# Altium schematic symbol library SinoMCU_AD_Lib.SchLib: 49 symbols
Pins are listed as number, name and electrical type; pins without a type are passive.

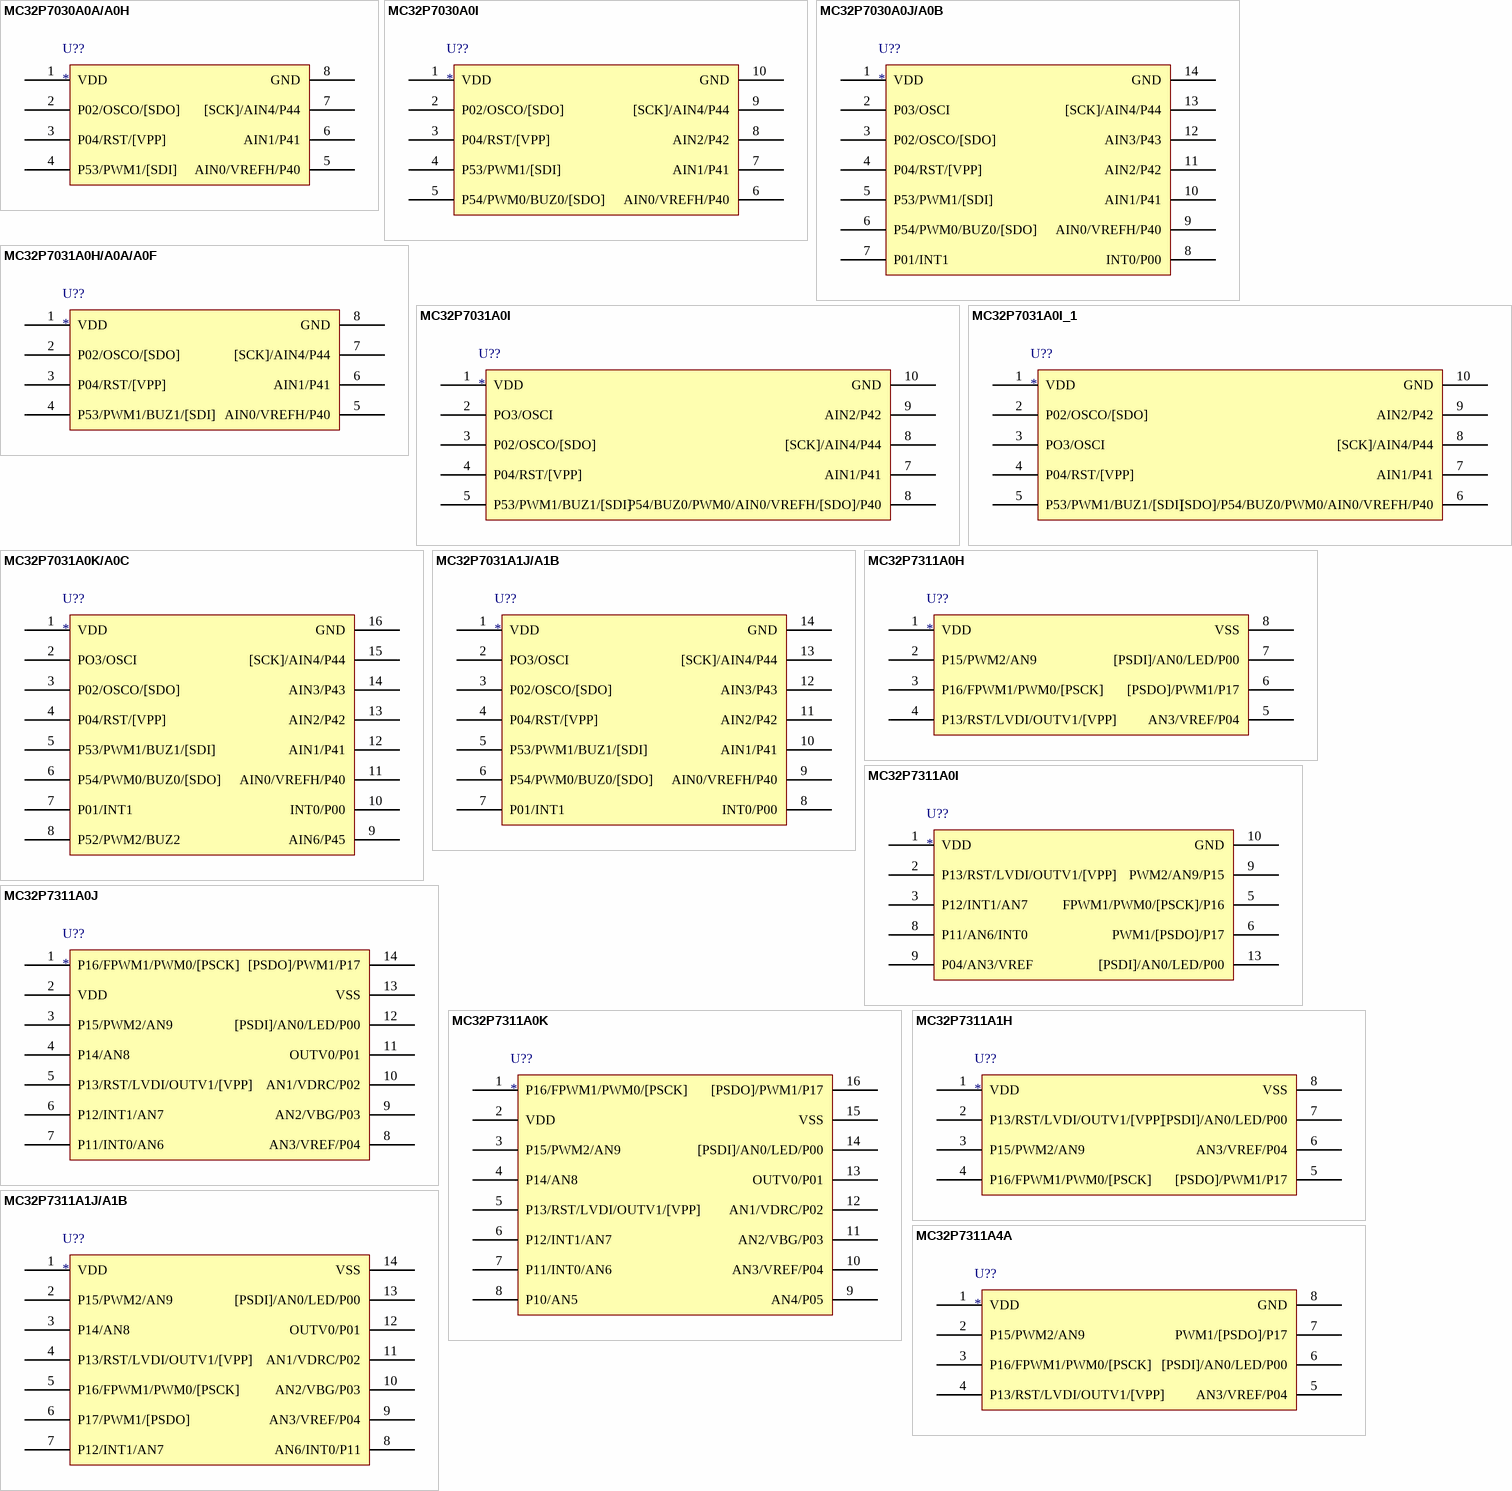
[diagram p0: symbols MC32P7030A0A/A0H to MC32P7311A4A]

## MC32P7030A0A/A0H
designator U??
pins: 1 VDD, 2 P02/OSCO/[SDO], 3 P04/RST/[VPP], 4 P53/PWM1/[SDI], 5 AIN0/VREFH/P40, 6 AIN1/P41, 7 [SCK]/AIN4/P44, 8 GND

## MC32P7030A0I
designator U??
pins: 1 VDD, 2 P02/OSCO/[SDO], 3 P04/RST/[VPP], 4 P53/PWM1/[SDI], 5 P54/PWM0/BUZ0/[SDO], 6 AIN0/VREFH/P40, 7 AIN1/P41, 8 AIN2/P42, 9 [SCK]/AIN4/P44, 10 GND

## MC32P7030A0J/A0B
designator U??
pins: 1 VDD, 2 P03/OSCI, 3 P02/OSCO/[SDO], 4 P04/RST/[VPP], 5 P53/PWM1/[SDI], 6 P54/PWM0/BUZ0/[SDO], 7 P01/INT1, 8 INT0/P00, 9 AIN0/VREFH/P40, 10 AIN1/P41, 11 AIN2/P42, 12 AIN3/P43, 13 [SCK]/AIN4/P44, 14 GND

## MC32P7031A0H/A0A/A0F
designator U??
pins: 1 VDD, 2 P02/OSCO/[SDO], 3 P04/RST/[VPP], 4 P53/PWM1/BUZ1/[SDI], 5 AIN0/VREFH/P40, 6 AIN1/P41, 7 [SCK]/AIN4/P44, 8 GND

## MC32P7031A0I
designator U??
pins: 1 VDD, 2 PO3/OSCI, 3 P02/OSCO/[SDO], 4 P04/RST/[VPP], 5 P53/PWM1/BUZ1/[SDI], 7 AIN1/P41, 8 P54/BUZ0/PWM0/AIN0/VREFH/[SDO]/P40, 8 [SCK]/AIN4/P44, 9 AIN2/P42, 10 GND

## MC32P7031A0I_1
designator U??
pins: 1 VDD, 2 P02/OSCO/[SDO], 3 PO3/OSCI, 4 P04/RST/[VPP], 5 P53/PWM1/BUZ1/[SDI], 6 [SDO]/P54/BUZ0/PWM0/AIN0/VREFH/P40, 7 AIN1/P41, 8 [SCK]/AIN4/P44, 9 AIN2/P42, 10 GND

## MC32P7031A0K/A0C
designator U??
pins: 1 VDD, 2 PO3/OSCI, 3 P02/OSCO/[SDO], 4 P04/RST/[VPP], 5 P53/PWM1/BUZ1/[SDI], 6 P54/PWM0/BUZ0/[SDO], 7 P01/INT1, 8 P52/PWM2/BUZ2, 9 AIN6/P45, 10 INT0/P00, 11 AIN0/VREFH/P40, 12 AIN1/P41, 13 AIN2/P42, 14 AIN3/P43, 15 [SCK]/AIN4/P44, 16 GND

## MC32P7031A1J/A1B
designator U??
pins: 1 VDD, 2 PO3/OSCI, 3 P02/OSCO/[SDO], 4 P04/RST/[VPP], 5 P53/PWM1/BUZ1/[SDI], 6 P54/PWM0/BUZ0/[SDO], 7 P01/INT1, 8 INT0/P00, 9 AIN0/VREFH/P40, 10 AIN1/P41, 11 AIN2/P42, 12 AIN3/P43, 13 [SCK]/AIN4/P44, 14 GND

## MC32P7311A0H
designator U??
pins: 1 VDD, 2 P15/PWM2/AN9, 3 P16/FPWM1/PWM0/[PSCK], 4 P13/RST/LVDI/OUTV1/[VPP], 5 AN3/VREF/P04, 6 [PSDO]/PWM1/P17, 7 [PSDI]/AN0/LED/P00, 8 VSS

## MC32P7311A0I
designator U??
pins: 1 VDD, 2 P13/RST/LVDI/OUTV1/[VPP], 3 P12/INT1/AN7, 5 FPWM1/PWM0/[PSCK]/P16, 6 PWM1/[PSDO]/P17, 8 P11/AN6/INT0, 9 PWM2/AN9/P15, 9 P04/AN3/VREF, 10 GND, 13 [PSDI]/AN0/LED/P00

## MC32P7311A0J
designator U??
pins: 1 P16/FPWM1/PWM0/[PSCK], 2 VDD, 3 P15/PWM2/AN9, 4 P14/AN8, 5 P13/RST/LVDI/OUTV1/[VPP], 6 P12/INT1/AN7, 7 P11/INT0/AN6, 8 AN3/VREF/P04, 9 AN2/VBG/P03, 10 AN1/VDRC/P02, 11 OUTV0/P01, 12 [PSDI]/AN0/LED/P00, 13 VSS, 14 [PSDO]/PWM1/P17

## MC32P7311A0K
designator U??
pins: 1 P16/FPWM1/PWM0/[PSCK], 2 VDD, 3 P15/PWM2/AN9, 4 P14/AN8, 5 P13/RST/LVDI/OUTV1/[VPP], 6 P12/INT1/AN7, 7 P11/INT0/AN6, 8 P10/AN5, 9 AN4/P05, 10 AN3/VREF/P04, 11 AN2/VBG/P03, 12 AN1/VDRC/P02, 13 OUTV0/P01, 14 [PSDI]/AN0/LED/P00, 15 VSS, 16 [PSDO]/PWM1/P17

## MC32P7311A1H
designator U??
pins: 1 VDD, 2 P13/RST/LVDI/OUTV1/[VPP], 3 P15/PWM2/AN9, 4 P16/FPWM1/PWM0/[PSCK], 5 [PSDO]/PWM1/P17, 6 AN3/VREF/P04, 7 [PSDI]/AN0/LED/P00, 8 VSS

## MC32P7311A1J/A1B
designator U??
pins: 1 VDD, 2 P15/PWM2/AN9, 3 P14/AN8, 4 P13/RST/LVDI/OUTV1/[VPP], 5 P16/FPWM1/PWM0/[PSCK], 6 P17/PWM1/[PSDO], 7 P12/INT1/AN7, 8 AN6/INT0/P11, 9 AN3/VREF/P04, 10 AN2/VBG/P03, 11 AN1/VDRC/P02, 12 OUTV0/P01, 13 [PSDI]/AN0/LED/P00, 14 VSS

## MC32P7311A4A
designator U??
pins: 1 VDD, 2 P15/PWM2/AN9, 3 P16/FPWM1/PWM0/[PSCK], 4 P13/RST/LVDI/OUTV1/[VPP], 5 AN3/VREF/P04, 6 [PSDI]/AN0/LED/P00, 7 PWM1/[PSDO]/P17, 8 GND

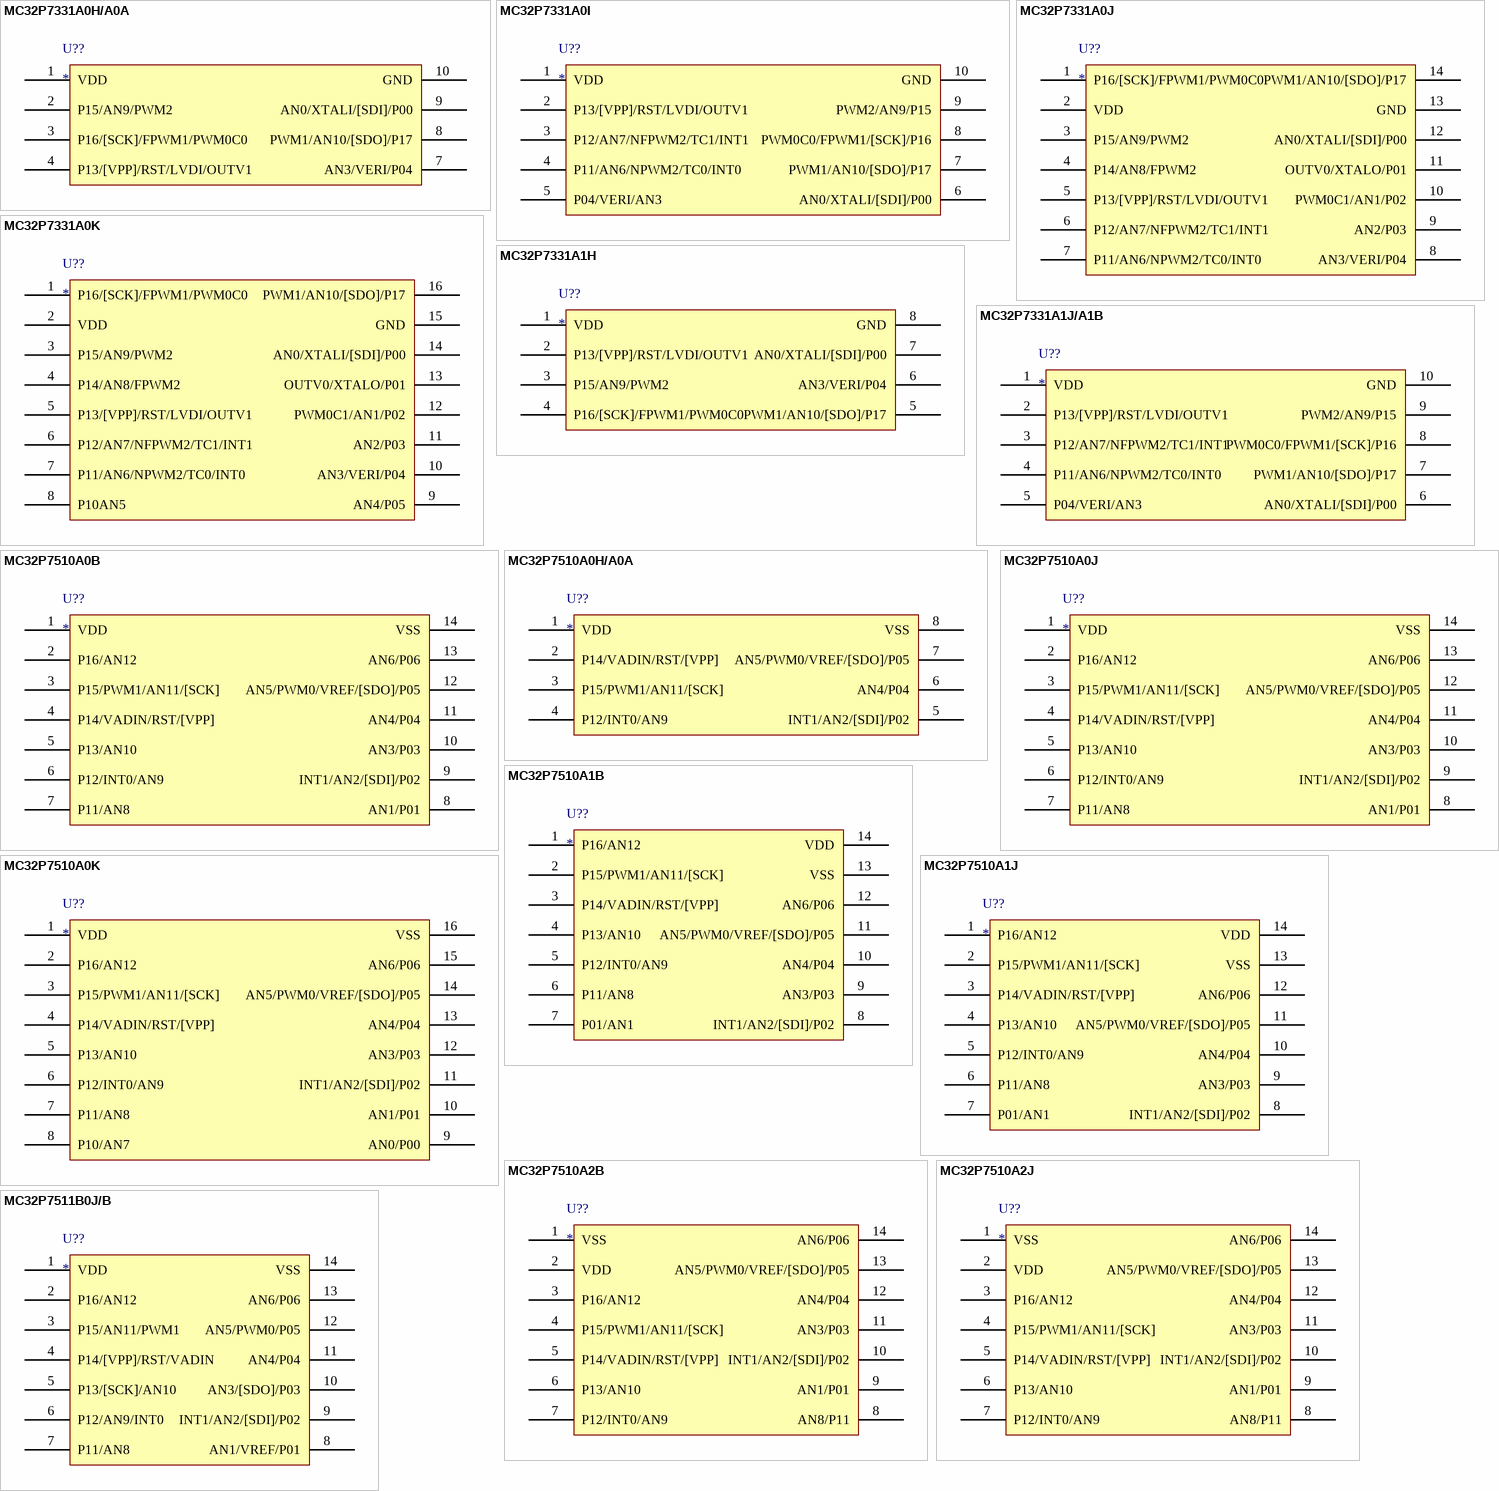
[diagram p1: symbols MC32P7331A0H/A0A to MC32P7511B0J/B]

## MC32P7331A0H/A0A
designator U??
pins: 1 VDD, 2 P15/AN9/PWM2, 3 P16/[SCK]/FPWM1/PWM0C0, 4 P13/[VPP]/RST/LVDI/OUTV1, 7 AN3/VERI/P04, 8 PWM1/AN10/[SDO]/P17, 9 AN0/XTALI/[SDI]/P00, 10 GND

## MC32P7331A0I
designator U??
pins: 1 VDD, 2 P13/[VPP]/RST/LVDI/OUTV1, 3 P12/AN7/NFPWM2/TC1/INT1, 4 P11/AN6/NPWM2/TC0/INT0, 5 P04/VERI/AN3, 6 AN0/XTALI/[SDI]/P00, 7 PWM1/AN10/[SDO]/P17, 8 PWM0C0/FPWM1/[SCK]/P16, 9 PWM2/AN9/P15, 10 GND

## MC32P7331A0J
designator U??
pins: 1 P16/[SCK]/FPWM1/PWM0C0, 2 VDD, 3 P15/AN9/PWM2, 4 P14/AN8/FPWM2, 5 P13/[VPP]/RST/LVDI/OUTV1, 6 P12/AN7/NFPWM2/TC1/INT1, 7 P11/AN6/NPWM2/TC0/INT0, 8 AN3/VERI/P04, 9 AN2/P03, 10 PWM0C1/AN1/P02, 11 OUTV0/XTALO/P01, 12 AN0/XTALI/[SDI]/P00, 13 GND, 14 PWM1/AN10/[SDO]/P17

## MC32P7331A0K
designator U??
pins: 1 P16/[SCK]/FPWM1/PWM0C0, 2 VDD, 3 P15/AN9/PWM2, 4 P14/AN8/FPWM2, 5 P13/[VPP]/RST/LVDI/OUTV1, 6 P12/AN7/NFPWM2/TC1/INT1, 7 P11/AN6/NPWM2/TC0/INT0, 8 P10AN5, 9 AN4/P05, 10 AN3/VERI/P04, 11 AN2/P03, 12 PWM0C1/AN1/P02, 13 OUTV0/XTALO/P01, 14 AN0/XTALI/[SDI]/P00, 15 GND, 16 PWM1/AN10/[SDO]/P17

## MC32P7331A1H
designator U??
pins: 1 VDD, 2 P13/[VPP]/RST/LVDI/OUTV1, 3 P15/AN9/PWM2, 4 P16/[SCK]/FPWM1/PWM0C0, 5 PWM1/AN10/[SDO]/P17, 6 AN3/VERI/P04, 7 AN0/XTALI/[SDI]/P00, 8 GND

## MC32P7331A1J/A1B
designator U??
pins: 1 VDD, 2 P13/[VPP]/RST/LVDI/OUTV1, 3 P12/AN7/NFPWM2/TC1/INT1, 4 P11/AN6/NPWM2/TC0/INT0, 5 P04/VERI/AN3, 6 AN0/XTALI/[SDI]/P00, 7 PWM1/AN10/[SDO]/P17, 8 PWM0C0/FPWM1/[SCK]/P16, 9 PWM2/AN9/P15, 10 GND

## MC32P7510A0B
designator U??
pins: 1 VDD, 2 P16/AN12, 3 P15/PWM1/AN11/[SCK], 4 P14/VADIN/RST/[VPP], 5 P13/AN10, 6 P12/INT0/AN9, 7 P11/AN8, 8 AN1/P01, 9 INT1/AN2/[SDI]/P02, 10 AN3/P03, 11 AN4/P04, 12 AN5/PWM0/VREF/[SDO]/P05, 13 AN6/P06, 14 VSS

## MC32P7510A0H/A0A
designator U??
pins: 1 VDD, 2 P14/VADIN/RST/[VPP], 3 P15/PWM1/AN11/[SCK], 4 P12/INT0/AN9, 5 INT1/AN2/[SDI]/P02, 6 AN4/P04, 7 AN5/PWM0/VREF/[SDO]/P05, 8 VSS

## MC32P7510A0J
designator U??
pins: 1 VDD, 2 P16/AN12, 3 P15/PWM1/AN11/[SCK], 4 P14/VADIN/RST/[VPP], 5 P13/AN10, 6 P12/INT0/AN9, 7 P11/AN8, 8 AN1/P01, 9 INT1/AN2/[SDI]/P02, 10 AN3/P03, 11 AN4/P04, 12 AN5/PWM0/VREF/[SDO]/P05, 13 AN6/P06, 14 VSS

## MC32P7510A0K
designator U??
pins: 1 VDD, 2 P16/AN12, 3 P15/PWM1/AN11/[SCK], 4 P14/VADIN/RST/[VPP], 5 P13/AN10, 6 P12/INT0/AN9, 7 P11/AN8, 8 P10/AN7, 9 AN0/P00, 10 AN1/P01, 11 INT1/AN2/[SDI]/P02, 12 AN3/P03, 13 AN4/P04, 14 AN5/PWM0/VREF/[SDO]/P05, 15 AN6/P06, 16 VSS

## MC32P7510A1B
designator U??
pins: 1 P16/AN12, 2 P15/PWM1/AN11/[SCK], 3 P14/VADIN/RST/[VPP], 4 P13/AN10, 5 P12/INT0/AN9, 6 P11/AN8, 7 P01/AN1, 8 INT1/AN2/[SDI]/P02, 9 AN3/P03, 10 AN4/P04, 11 AN5/PWM0/VREF/[SDO]/P05, 12 AN6/P06, 13 VSS, 14 VDD

## MC32P7510A1J
designator U??
pins: 1 P16/AN12, 2 P15/PWM1/AN11/[SCK], 3 P14/VADIN/RST/[VPP], 4 P13/AN10, 5 P12/INT0/AN9, 6 P11/AN8, 7 P01/AN1, 8 INT1/AN2/[SDI]/P02, 9 AN3/P03, 10 AN4/P04, 11 AN5/PWM0/VREF/[SDO]/P05, 12 AN6/P06, 13 VSS, 14 VDD

## MC32P7510A2B
designator U??
pins: 1 VSS, 2 VDD, 3 P16/AN12, 4 P15/PWM1/AN11/[SCK], 5 P14/VADIN/RST/[VPP], 6 P13/AN10, 7 P12/INT0/AN9, 8 AN8/P11, 9 AN1/P01, 10 INT1/AN2/[SDI]/P02, 11 AN3/P03, 12 AN4/P04, 13 AN5/PWM0/VREF/[SDO]/P05, 14 AN6/P06

## MC32P7510A2J
designator U??
pins: 1 VSS, 2 VDD, 3 P16/AN12, 4 P15/PWM1/AN11/[SCK], 5 P14/VADIN/RST/[VPP], 6 P13/AN10, 7 P12/INT0/AN9, 8 AN8/P11, 9 AN1/P01, 10 INT1/AN2/[SDI]/P02, 11 AN3/P03, 12 AN4/P04, 13 AN5/PWM0/VREF/[SDO]/P05, 14 AN6/P06

## MC32P7511B0J/B
designator U??
pins: 1 VDD, 2 P16/AN12, 3 P15/AN11/PWM1, 4 P14/[VPP]/RST/VADIN, 5 P13/[SCK]/AN10, 6 P12/AN9/INT0, 7 P11/AN8, 8 AN1/VREF/P01, 9 INT1/AN2/[SDI]/P02, 10 AN3/[SDO]/P03, 11 AN4/P04, 12 AN5/PWM0/P05, 13 AN6/P06, 14 VSS

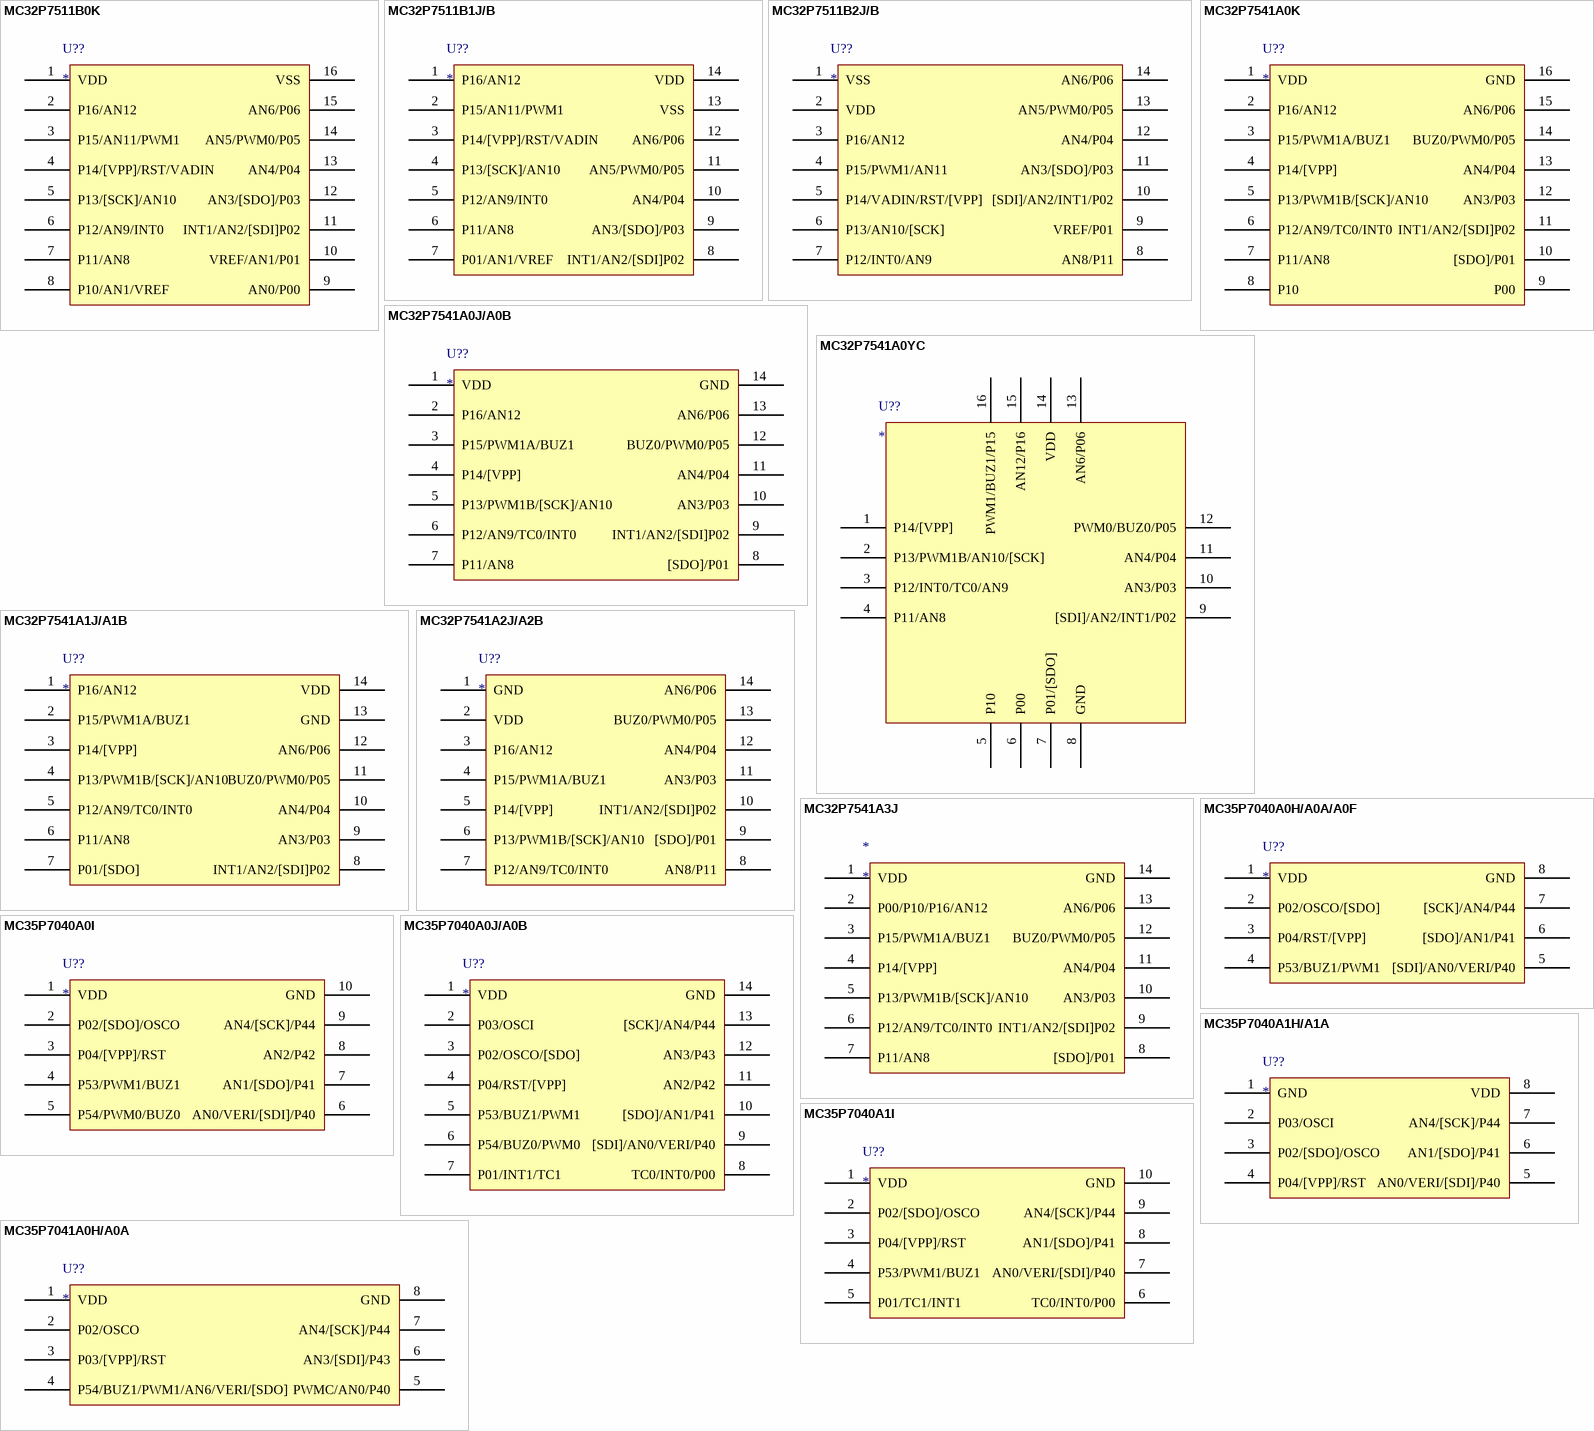
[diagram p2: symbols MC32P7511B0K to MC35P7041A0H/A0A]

## MC32P7511B0K
designator U??
pins: 1 0 hidden, 1 VDD, 2 P16/AN12, 3 P15/AN11/PWM1, 4 P14/[VPP]/RST/VADIN, 5 P13/[SCK]/AN10, 6 P12/AN9/INT0, 7 P11/AN8, 8 P10/AN1/VREF, 9 AN0/P00, 10 VREF/AN1/P01, 11 INT1/AN2/[SDI]P02, 12 AN3/[SDO]/P03, 13 AN4/P04, 14 AN5/PWM0/P05, 15 AN6/P06, 16 VSS

## MC32P7511B1J/B
designator U??
pins: 1 P16/AN12, 2 P15/AN11/PWM1, 3 P14/[VPP]/RST/VADIN, 4 P13/[SCK]/AN10, 5 P12/AN9/INT0, 6 P11/AN8, 7 P01/AN1/VREF, 8 INT1/AN2/[SDI]P02, 9 AN3/[SDO]/P03, 10 AN4/P04, 11 AN5/PWM0/P05, 12 AN6/P06, 13 VSS, 14 VDD

## MC32P7511B2J/B
designator U??
pins: 1 VSS, 2 VDD, 3 P16/AN12, 4 P15/PWM1/AN11, 5 P14/VADIN/RST/[VPP], 6 P13/AN10/[SCK], 7 P12/INT0/AN9, 8 AN8/P11, 9 VREF/P01, 10 [SDI]/AN2/INT1/P02, 11 AN3/[SDO]/P03, 12 AN4/P04, 13 AN5/PWM0/P05, 14 AN6/P06

## MC32P7541A0J/A0B
designator U??
pins: 1 VDD, 2 P16/AN12, 3 P15/PWM1A/BUZ1, 4 P14/[VPP], 5 P13/PWM1B/[SCK]/AN10, 6 P12/AN9/TC0/INT0, 7 P11/AN8, 8 [SDO]/P01, 9 INT1/AN2/[SDI]P02, 10 AN3/P03, 11 AN4/P04, 12 BUZ0/PWM0/P05, 13 AN6/P06, 14 GND

## MC32P7541A0K
designator U??
pins: 1 VDD, 2 P16/AN12, 3 P15/PWM1A/BUZ1, 4 P14/[VPP], 5 P13/PWM1B/[SCK]/AN10, 6 P12/AN9/TC0/INT0, 7 P11/AN8, 8 P10, 9 P00, 10 [SDO]/P01, 11 INT1/AN2/[SDI]P02, 12 AN3/P03, 13 AN4/P04, 14 BUZ0/PWM0/P05, 15 AN6/P06, 16 GND

## MC32P7541A0YC
designator U??
pins: 1 P14/[VPP], 2 P13/PWM1B/AN10/[SCK], 3 P12/INT0/TC0/AN9, 4 P11/AN8, 5 P10, 6 P00, 7 P01/[SDO], 8 GND, 9 [SDI]/AN2/INT1/P02, 10 AN3/P03, 11 AN4/P04, 12 PWM0/BUZ0/P05, 13 AN6/P06, 14 VDD, 15 AN12/P16, 16 PWM1/BUZ1/P15

## MC32P7541A1J/A1B
designator U??
pins: 1 P16/AN12, 2 P15/PWM1A/BUZ1, 3 P14/[VPP], 4 P13/PWM1B/[SCK]/AN10, 5 P12/AN9/TC0/INT0, 6 P11/AN8, 7 P01/[SDO], 8 INT1/AN2/[SDI]P02, 9 AN3/P03, 10 AN4/P04, 11 BUZ0/PWM0/P05, 12 AN6/P06, 13 GND, 14 VDD

## MC32P7541A2J/A2B
designator U??
pins: 1 GND, 2 VDD, 3 P16/AN12, 4 P15/PWM1A/BUZ1, 5 P14/[VPP], 6 P13/PWM1B/[SCK]/AN10, 7 P12/AN9/TC0/INT0, 8 AN8/P11, 9 [SDO]/P01, 10 INT1/AN2/[SDI]P02, 11 AN3/P03, 12 AN4/P04, 13 BUZ0/PWM0/P05, 14 AN6/P06

## MC32P7541A3J
designator *
pins: 1 VDD, 2 P00/P10/P16/AN12, 3 P15/PWM1A/BUZ1, 4 P14/[VPP], 5 P13/PWM1B/[SCK]/AN10, 6 P12/AN9/TC0/INT0, 7 P11/AN8, 8 [SDO]/P01, 9 INT1/AN2/[SDI]P02, 10 AN3/P03, 11 AN4/P04, 12 BUZ0/PWM0/P05, 13 AN6/P06, 14 GND

## MC35P7040A0H/A0A/A0F
designator U??
pins: 1 VDD, 2 P02/OSCO/[SDO], 3 P04/RST/[VPP], 4 P53/BUZ1/PWM1, 5 [SDI]/AN0/VERI/P40, 6 [SDO]/AN1/P41, 7 [SCK]/AN4/P44, 8 GND

## MC35P7040A0I
designator U??
pins: 1 VDD, 2 P02/[SDO]/OSCO, 3 P04/[VPP]/RST, 4 P53/PWM1/BUZ1, 5 P54/PWM0/BUZ0, 6 AN0/VERI/[SDI]/P40, 7 AN1/[SDO]/P41, 8 AN2/P42, 9 AN4/[SCK]/P44, 10 GND

## MC35P7040A0J/A0B
designator U??
pins: 1 VDD, 2 P03/OSCI, 3 P02/OSCO/[SDO], 4 P04/RST/[VPP], 5 P53/BUZ1/PWM1, 6 P54/BUZ0/PWM0, 7 P01/INT1/TC1, 8 TC0/INT0/P00, 9 [SDI]/AN0/VERI/P40, 10 [SDO]/AN1/P41, 11 AN2/P42, 12 AN3/P43, 13 [SCK]/AN4/P44, 14 GND

## MC35P7040A1H/A1A
designator U??
pins: 1 GND, 2 P03/OSCI, 3 P02/[SDO]/OSCO, 4 P04/[VPP]/RST, 5 AN0/VERI/[SDI]/P40, 6 AN1/[SDO]/P41, 7 AN4/[SCK]/P44, 8 VDD

## MC35P7040A1I
designator U??
pins: 1 VDD, 2 P02/[SDO]/OSCO, 3 P04/[VPP]/RST, 4 P53/PWM1/BUZ1, 5 P01/TC1/INT1, 6 TC0/INT0/P00, 7 AN0/VERI/[SDI]/P40, 8 AN1/[SDO]/P41, 9 AN4/[SCK]/P44, 10 GND

## MC35P7041A0H/A0A
designator U??
pins: 1 VDD, 2 P02/OSCO, 3 P03/[VPP]/RST, 4 P54/BUZ1/PWM1/AN6/VERI/[SDO], 5 PWMC/AN0/P40, 6 AN3/[SDI]/P43, 7 AN4/[SCK]/P44, 8 GND

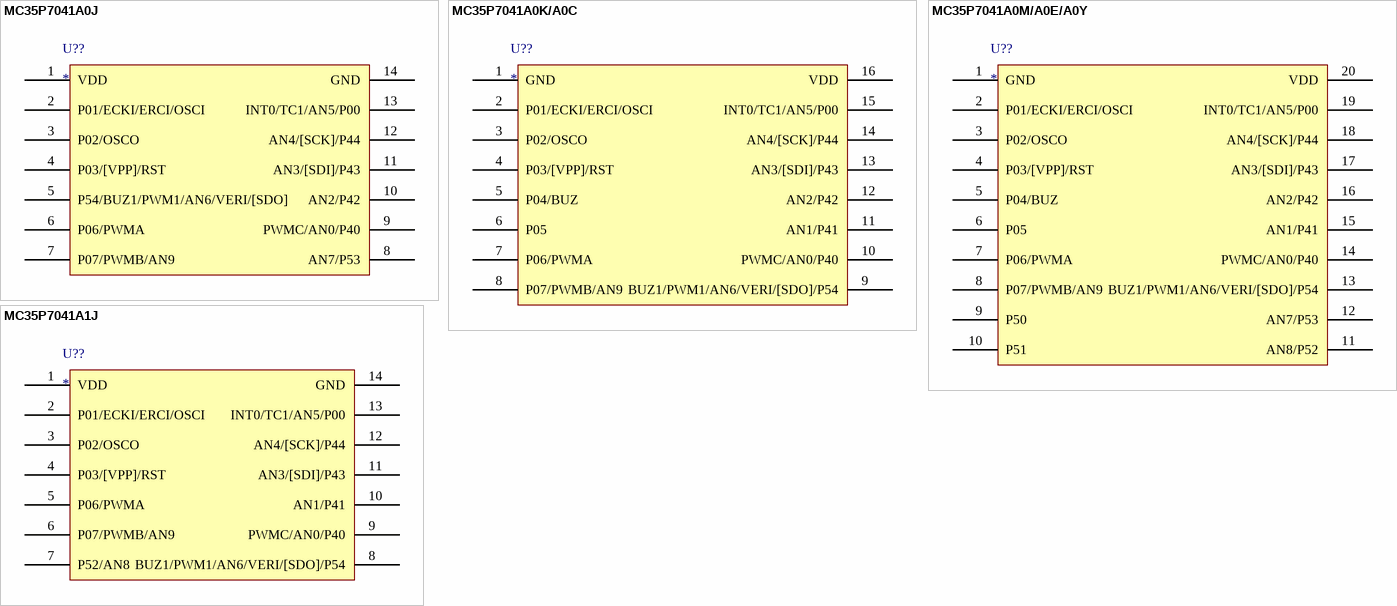
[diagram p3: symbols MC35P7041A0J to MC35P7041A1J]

## MC35P7041A0J
designator U??
pins: 1 VDD, 2 P01/ECKI/ERCI/OSCI, 3 P02/OSCO, 4 P03/[VPP]/RST, 5 P54/BUZ1/PWM1/AN6/VERI/[SDO], 6 P06/PWMA, 7 P07/PWMB/AN9, 8 AN7/P53, 9 PWMC/AN0/P40, 10 AN2/P42, 11 AN3/[SDI]/P43, 12 AN4/[SCK]/P44, 13 INT0/TC1/AN5/P00, 14 GND

## MC35P7041A0K/A0C
designator U??
pins: 1 GND, 2 P01/ECKI/ERCI/OSCI, 3 P02/OSCO, 4 P03/[VPP]/RST, 5 P04/BUZ, 6 P05, 7 P06/PWMA, 8 P07/PWMB/AN9, 9 BUZ1/PWM1/AN6/VERI/[SDO]/P54, 10 PWMC/AN0/P40, 11 AN1/P41, 12 AN2/P42, 13 AN3/[SDI]/P43, 14 AN4/[SCK]/P44, 15 INT0/TC1/AN5/P00, 16 VDD

## MC35P7041A0M/A0E/A0Y
designator U??
pins: 1 GND, 2 P01/ECKI/ERCI/OSCI, 3 P02/OSCO, 4 P03/[VPP]/RST, 5 P04/BUZ, 6 P05, 7 P06/PWMA, 8 P07/PWMB/AN9, 9 P50, 10 P51, 11 AN8/P52, 12 AN7/P53, 13 BUZ1/PWM1/AN6/VERI/[SDO]/P54, 14 PWMC/AN0/P40, 15 AN1/P41, 16 AN2/P42, 17 AN3/[SDI]/P43, 18 AN4/[SCK]/P44, 19 INT0/TC1/AN5/P00, 20 VDD

## MC35P7041A1J
designator U??
pins: 1 VDD, 2 P01/ECKI/ERCI/OSCI, 3 P02/OSCO, 4 P03/[VPP]/RST, 5 P06/PWMA, 6 P07/PWMB/AN9, 7 P52/AN8, 8 BUZ1/PWM1/AN6/VERI/[SDO]/P54, 9 PWMC/AN0/P40, 10 AN1/P41, 11 AN3/[SDI]/P43, 12 AN4/[SCK]/P44, 13 INT0/TC1/AN5/P00, 14 GND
